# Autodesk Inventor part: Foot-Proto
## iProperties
Created: 2009-01
Part Number: Foot-Proto
Material: Aluminum-6061
Document SubType Name: Sheet Metal
Designer: Administrator
Density: 1 g/cm^3
Author: Administrator
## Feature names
1. Corner Chamfer2
2. Corner Chamfer3
3. Corner Chamfer4
4. Hole2
5. Hole3
6. Plate1
7. Plate2
8. Bend1
9. Plate3
10. Bend2
11. Plate4
12. Bend3
13. Plate5
14. Bend4
15. Plate6
16. Bend5
17. Plate9
18. Bend8
19. Plate10
20. Bend9
21. Cut2
22. Cut3
23. Cut4
